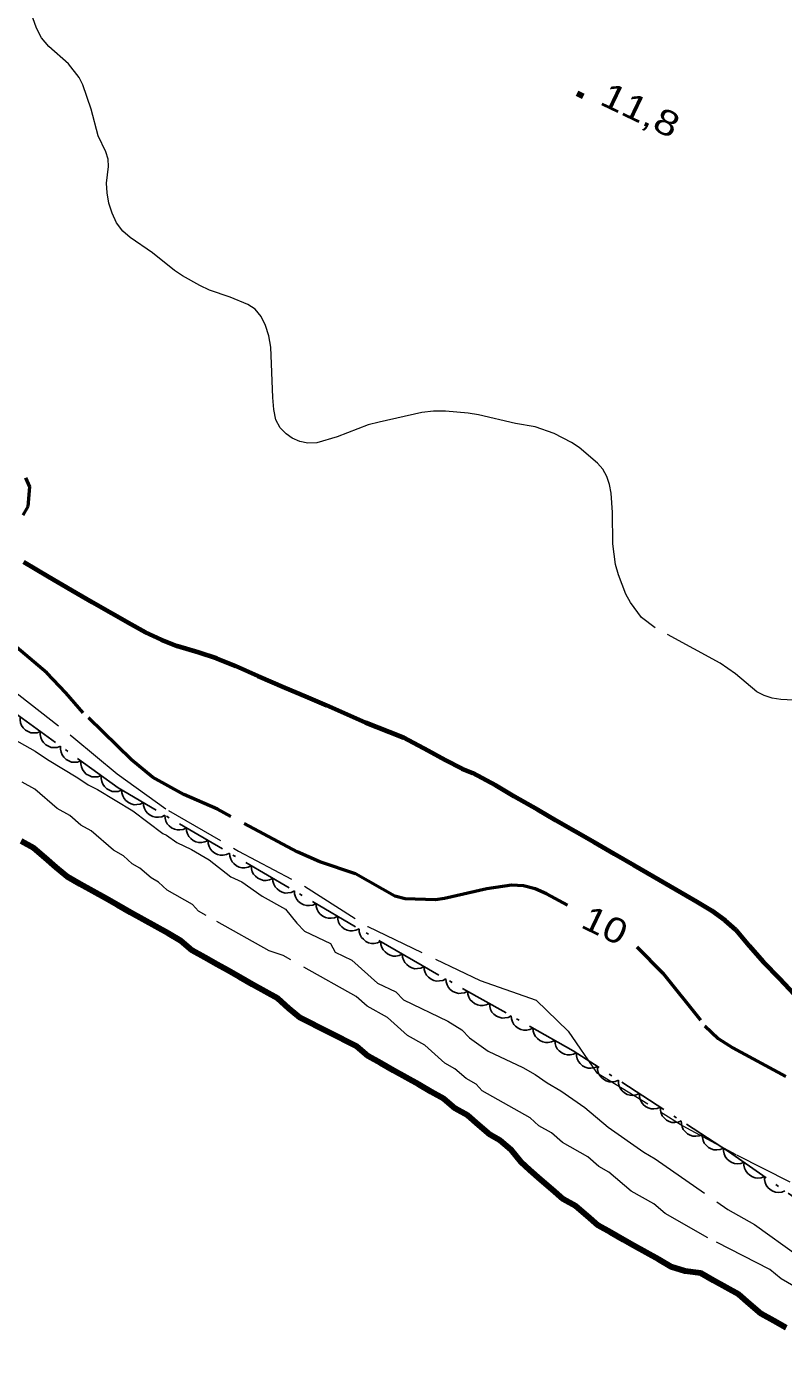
# Model space of a CAD drawing. Extents: x 355726 to 357533, y 5103782 to 5105258.
# Drawn here: x 356113.8 to 356159.2, y 5104614.8 to 5104694.4 of the extents above; entities that cross this region are included whole.
import ezdxf
from ezdxf.enums import TextEntityAlignment as Align

# ---------------------------------------------------------------- set-up
doc = ezdxf.new("R2010")
doc.units = 0
doc.header["$LTSCALE"] = 0.6
for name, pattern in [('DASH_DOUBLE_DOT', [9.2, 5, -1.2, 0.3, -1.2, 0.3, -1.2]), ('DOT_DASHED', [7.7, 5, -1.2, 0.3, -1.2]), ('LONG_DASHED', [7.5, 6, -1.5])]:
    doc.linetypes.add(name, pattern=pattern)
for name, color, linetype, lineweight in [('1', 7, 'LONG_DASHED', 53), ('2', 7, 'LONG_DASHED', 13), ('22', 7, 'Continuous', 13), ('3', 7, 'Continuous', 140), ('4', 7, 'DASH_DOUBLE_DOT', 53), ('44', 7, 'Continuous', 25)]:
    doc.layers.add(name, color=color, linetype=linetype, lineweight=lineweight)

msp = doc.modelspace()

# ---------------------------------------------------------------- linework, layer by layer
at = {"layer": '1'}
for points in [[(356113.61, 5104665.13), (356113.92, 5104665.65), (356114.02, 5104666.84), (356113.78, 5104667.37)], [(356146.26, 5104641.76), (356145, 5104642.44), (356144.32, 5104642.73), (356143.62, 5104642.91), (356142.89, 5104642.96), (356141.42, 5104642.74), (356138.88, 5104642.15), (356138.33, 5104642.07), (356136.52, 5104642.13), (356135.91, 5104642.3), (356133.55, 5104643.63), (356131.4, 5104644.36), (356130.04, 5104644.96), (356125.26, 5104647.51), (356123.25, 5104648.38), (356121.37, 5104649.42), (356120.1, 5104650.46), (356117.22, 5104653.28), (356116.18, 5104654.48), (356115.03, 5104655.69), (356113.22, 5104657.23)], [(356150.42, 5104639.25), (356151.98, 5104637.68), (356154.5, 5104634.53), (356155.29, 5104633.76), (356156.17, 5104633.2), (356161.44, 5104630.36)]]:
    msp.add_lwpolyline(points, dxfattribs=at)
at = {"layer": '2'}
for points in [[(356127.53, 5104677.49), (356127.09, 5104677.76), (356126.02, 5104678.21), (356124.79, 5104678.63), (356124.2, 5104678.9), (356123.16, 5104679.48), (356122.69, 5104679.8), (356121.37, 5104680.86), (356120.03, 5104681.78), (356119.58, 5104682.16), (356119.21, 5104682.67), (356118.94, 5104683.24), (356118.74, 5104683.84), (356118.64, 5104684.46), (356118.6, 5104685.04), (356118.73, 5104686.04), (356118.71, 5104686.48), (356118.57, 5104686.92), (356118.11, 5104687.87), (356117.69, 5104689.47), (356117.2, 5104690.93), (356116.98, 5104691.37), (356116.33, 5104692.19), (356115.15, 5104693.24), (356114.72, 5104693.76), (356114.41, 5104694.34), (356114.2, 5104694.95)], [(356161.17, 5104653.98), (356159.04, 5104654.08), (356158.52, 5104654.16), (356158.05, 5104654.32), (356157.61, 5104654.55), (356156.33, 5104655.63), (356155.42, 5104656.26), (356151.52, 5104658.38), (356150.7, 5104659.01), (356150.03, 5104659.9), (356149.76, 5104660.4), (356149.32, 5104661.55), (356149.14, 5104662.17), (356148.97, 5104663.42), (356148.95, 5104665.3), (356148.88, 5104666.45), (356148.77, 5104666.98), (356148.61, 5104667.46), (356148.38, 5104667.9), (356148.06, 5104668.25), (356146.96, 5104669.19), (356146.49, 5104669.49), (356145.45, 5104670.04), (356144.32, 5104670.43), (356143.13, 5104670.63), (356140.91, 5104671.16), (356140.29, 5104671.26), (356138.93, 5104671.38), (356138.22, 5104671.38), (356137.52, 5104671.3), (356134.96, 5104670.72), (356134.3, 5104670.55), (356132.45, 5104669.84), (356131.22, 5104669.48), (356130.68, 5104669.46), (356130.2, 5104669.55), (356129.75, 5104669.75), (356129.38, 5104670.01), (356129.02, 5104670.37), (356128.76, 5104670.86), (356128.64, 5104671.47), (356128.58, 5104672.19), (356128.46, 5104675.2), (356128.35, 5104675.88), (356128.14, 5104676.51), (356127.89, 5104677.05), (356127.53, 5104677.49)], [(356112.89, 5104654.73), (356116.65, 5104651.79), (356119.24, 5104649.63), (356122.32, 5104647.43), (356126.53, 5104645), (356130.48, 5104642.9), (356134.28, 5104640.47), (356141.02, 5104637.24), (356144.38, 5104636.05), (356146.29, 5104634.2), (356148, 5104631.73), (356153.18, 5104628.53), (356156.38, 5104626.79), (356159.96, 5104624.98)], [(356111.22, 5104652.72), (356114.34, 5104650.99), (356115.07, 5104650.48), (356116.9, 5104649.38), (356117.52, 5104648.96), (356118.07, 5104648.69), (356120.19, 5104647.42), (356121.98, 5104646.05), (356122.2, 5104645.95), (356122.82, 5104645.51), (356123.71, 5104645.09), (356124.77, 5104644.47), (356126.06, 5104643.46), (356126.72, 5104643.15), (356127.95, 5104642.3), (356129.34, 5104641.51), (356130.03, 5104640.67), (356130.49, 5104640.2), (356132.04, 5104639.45), (356132.33, 5104638.93), (356133.33, 5104638.45), (356134.86, 5104637.08), (356135.96, 5104636.55), (356136.42, 5104636.08), (356139.08, 5104634.8), (356139.92, 5104634.28), (356140.37, 5104633.8), (356141.49, 5104633.01), (356143.57, 5104632.02), (356144.32, 5104631.6), (356145.03, 5104631.1), (356145.86, 5104630.63), (356147.29, 5104629.63), (356148.7, 5104628.44), (356150.84, 5104626.94), (356151.52, 5104626.55), (356155.87, 5104623.51), (356157.46, 5104622.62), (356160.08, 5104620.74)], [(356159.82, 5104618.92), (356159.06, 5104619.35), (356158.39, 5104619.92), (356154.68, 5104621.82), (356152.11, 5104623.26), (356151.44, 5104623.84), (356150.08, 5104624.6), (356148.74, 5104625.75), (356148.14, 5104626.09), (356147.47, 5104626.67), (356145.96, 5104627.52), (356145.29, 5104628.1), (356144.53, 5104628.52), (356144.01, 5104629.01), (356141.14, 5104630.63), (356140.77, 5104631.03), (356140.17, 5104631.37), (356139.5, 5104631.95), (356138.89, 5104632.29), (356137.7, 5104633.36), (356136.65, 5104633.95), (356135.46, 5104635.02), (356134.25, 5104635.7), (356133.58, 5104636.27), (356129.2, 5104638.74), (356128.36, 5104639.02), (356124.58, 5104641.14), (356124.13, 5104641.4), (356123.76, 5104641.8), (356122.25, 5104642.65), (356121.73, 5104643.14), (356121.28, 5104643.4), (356120.61, 5104643.97), (356120.15, 5104644.23), (356119.63, 5104644.72), (356119.03, 5104645.06), (356117.69, 5104646.21), (356117.08, 5104646.55), (356116.41, 5104647.13), (356115.66, 5104647.55), (356114.32, 5104648.7), (356113.56, 5104649.13)]]:
    msp.add_lwpolyline(points, dxfattribs=at)
at = {"layer": '22', "linetype": 'LONG_DASHED', "lineweight": 70}
msp.add_lwpolyline([(356159.86, 5104636.4), (356158.98, 5104637.33), (356158.01, 5104638.34), (356157.17, 5104639.3), (356156.34, 5104640.28), (356155.7, 5104640.84), (356154.91, 5104641.41), (356154.02, 5104641.95), (356152.77, 5104642.67), (356151.39, 5104643.48), (356150.26, 5104644.13), (356149.07, 5104644.82), (356147.87, 5104645.51), (356146.71, 5104646.18), (356145.56, 5104646.84), (356144.47, 5104647.47), (356143.05, 5104648.28), (356141.95, 5104648.92), (356140.57, 5104649.66), (356139.94, 5104649.93), (356138.92, 5104650.44), (356137.9, 5104651), (356136.44, 5104651.78), (356135.58, 5104652.13), (356134.17, 5104652.68), (356133.05, 5104653.19), (356131.83, 5104653.73), (356130.56, 5104654.26), (356129.33, 5104654.78), (356127.71, 5104655.49), (356126.36, 5104656.09), (356125.22, 5104656.54), (356124.12, 5104656.9), (356122.85, 5104657.28), (356121.9, 5104657.67), (356120.94, 5104658.11), (356120.08, 5104658.58), (356118.93, 5104659.24), (356117.76, 5104659.91), (356116.53, 5104660.62), (356115.14, 5104661.43), (356113.66, 5104662.32)], dxfattribs=at)
at = {"layer": '3'}
msp.add_line((356146.83, 5104690.43), (356147.19, 5104690.26), dxfattribs=at)
at = {"layer": '4', "linetype": 'Continuous', "lineweight": 90}
for points in [[(356143.99, 5104625.86), (356143.47, 5104626.35), (356142.88, 5104627.08), (356142.21, 5104627.65), (356141.61, 5104627.99), (356140.94, 5104628.57), (356140.27, 5104629.15), (356139.51, 5104629.57), (356138.84, 5104630.15), (356138.08, 5104630.57), (356137.33, 5104631), (356136.57, 5104631.42), (356135.82, 5104631.85), (356135.06, 5104632.28), (356134.3, 5104632.7), (356133.63, 5104633.28), (356130.22, 5104635), (356129.55, 5104635.57), (356128.88, 5104636.15), (356128.13, 5104636.58), (356127.37, 5104637), (356126.61, 5104637.43), (356125.86, 5104637.85), (356125.25, 5104638.19), (356124.5, 5104638.62), (356123.74, 5104639.04), (356123.07, 5104639.62), (356122.32, 5104640.05), (356121.56, 5104640.47), (356120.8, 5104640.9), (356120.05, 5104641.32), (356119.29, 5104641.75), (356118.54, 5104642.17), (356117.78, 5104642.6), (356117.03, 5104643.02), (356116.27, 5104643.45), (356115.6, 5104644.02), (356114.93, 5104644.6), (356114.26, 5104645.18), (356113.5, 5104645.6)], [(356159.37, 5104616.41), (356158.62, 5104616.83), (356157.86, 5104617.26), (356157.19, 5104617.83), (356156.52, 5104618.41), (356155.76, 5104618.84), (356155.01, 5104619.26), (356154.25, 5104619.69), (356153.32, 5104619.81), (356152.48, 5104620.08), (356151.73, 5104620.51), (356150.97, 5104620.94), (356150.22, 5104621.36), (356149.61, 5104621.7), (356148.85, 5104622.13), (356148.1, 5104622.55), (356147.43, 5104623.13), (356146.76, 5104623.71), (356146, 5104624.13), (356145.33, 5104624.71), (356144.66, 5104625.28), (356143.99, 5104625.86)]]:
    msp.add_lwpolyline(points, dxfattribs=at)
at = {"layer": '44', "linetype": 'DOT_DASHED'}
msp.add_lwpolyline([(356173.31, 5104614.82), (356155.91, 5104626.99), (356146.6, 5104633.03), (356137.54, 5104638.13), (356119.3, 5104648.79), (356111.96, 5104654.11), (356105.36, 5104658.62), (356100.57, 5104662.11), (356094.1, 5104666.15), (356087.33, 5104670.35), (356082.24, 5104674.01), (356078.19, 5104676.69), (356069.01, 5104682.26)], dxfattribs=at)
at = {"layer": '44'}
for points in [[(356114.65, 5104652.16), (356114.45, 5104652.09), (356114.25, 5104652.08), (356114.08, 5104652.09), (356113.92, 5104652.16), (356113.76, 5104652.25), (356113.62, 5104652.39), (356113.52, 5104652.52), (356113.46, 5104652.68), (356113.43, 5104652.86), (356113.43, 5104653.04)], [(356115.86, 5104651.28), (356115.66, 5104651.21), (356115.46, 5104651.2), (356115.3, 5104651.21), (356115.13, 5104651.28), (356114.97, 5104651.37), (356114.84, 5104651.51), (356114.74, 5104651.64), (356114.68, 5104651.8), (356114.64, 5104651.98), (356114.65, 5104652.16)], [(356117.07, 5104650.4), (356116.88, 5104650.33), (356116.68, 5104650.32), (356116.51, 5104650.33), (356116.35, 5104650.4), (356116.19, 5104650.49), (356116.05, 5104650.63), (356115.95, 5104650.76), (356115.89, 5104650.92), (356115.85, 5104651.1), (356115.86, 5104651.28)], [(356118.29, 5104649.52), (356118.09, 5104649.45), (356117.89, 5104649.44), (356117.73, 5104649.45), (356117.56, 5104649.52), (356117.4, 5104649.61), (356117.27, 5104649.75), (356117.17, 5104649.88), (356117.11, 5104650.04), (356117.07, 5104650.22), (356117.07, 5104650.4)], [(356119.5, 5104648.64), (356119.31, 5104648.57), (356119.1, 5104648.56), (356118.94, 5104648.57), (356118.78, 5104648.64), (356118.62, 5104648.73), (356118.48, 5104648.87), (356118.38, 5104649), (356118.32, 5104649.16), (356118.28, 5104649.34), (356118.29, 5104649.52)], [(356120.81, 5104647.91), (356120.62, 5104647.82), (356120.42, 5104647.79), (356120.26, 5104647.78), (356120.09, 5104647.83), (356119.92, 5104647.91), (356119.77, 5104648.03), (356119.66, 5104648.15), (356119.58, 5104648.31), (356119.53, 5104648.48), (356119.52, 5104648.66)], [(356122.11, 5104647.15), (356121.92, 5104647.06), (356121.72, 5104647.03), (356121.55, 5104647.03), (356121.38, 5104647.07), (356121.22, 5104647.15), (356121.07, 5104647.27), (356120.96, 5104647.39), (356120.88, 5104647.55), (356120.82, 5104647.73), (356120.81, 5104647.91)], [(356123.4, 5104646.39), (356123.21, 5104646.3), (356123.01, 5104646.27), (356122.85, 5104646.27), (356122.68, 5104646.32), (356122.51, 5104646.39), (356122.36, 5104646.52), (356122.25, 5104646.63), (356122.17, 5104646.79), (356122.12, 5104646.97), (356122.11, 5104647.15)], [(356124.7, 5104645.64), (356124.51, 5104645.55), (356124.31, 5104645.51), (356124.14, 5104645.51), (356123.97, 5104645.56), (356123.81, 5104645.64), (356123.66, 5104645.76), (356123.55, 5104645.88), (356123.47, 5104646.04), (356123.41, 5104646.21), (356123.4, 5104646.39)], [(356125.99, 5104644.88), (356125.8, 5104644.79), (356125.6, 5104644.76), (356125.44, 5104644.75), (356125.27, 5104644.8), (356125.1, 5104644.88), (356124.95, 5104645), (356124.84, 5104645.12), (356124.76, 5104645.28), (356124.71, 5104645.46), (356124.7, 5104645.64)], [(356127.29, 5104644.12), (356127.1, 5104644.03), (356126.9, 5104644), (356126.73, 5104644), (356126.56, 5104644.04), (356126.4, 5104644.12), (356126.25, 5104644.25), (356126.14, 5104644.36), (356126.06, 5104644.52), (356126, 5104644.7), (356125.99, 5104644.88)], [(356128.58, 5104643.36), (356128.39, 5104643.27), (356128.19, 5104643.24), (356128.03, 5104643.24), (356127.86, 5104643.29), (356127.69, 5104643.37), (356127.54, 5104643.49), (356127.43, 5104643.61), (356127.35, 5104643.76), (356127.3, 5104643.94), (356127.29, 5104644.12)], [(356129.88, 5104642.61), (356129.69, 5104642.52), (356129.49, 5104642.49), (356129.32, 5104642.48), (356129.15, 5104642.53), (356128.99, 5104642.61), (356128.84, 5104642.73), (356128.73, 5104642.85), (356128.65, 5104643.01), (356128.59, 5104643.19), (356128.58, 5104643.36)], [(356131.17, 5104641.85), (356130.98, 5104641.76), (356130.78, 5104641.73), (356130.62, 5104641.73), (356130.45, 5104641.77), (356130.28, 5104641.85), (356130.13, 5104641.98), (356130.02, 5104642.09), (356129.94, 5104642.25), (356129.89, 5104642.43), (356129.88, 5104642.61)], [(356132.47, 5104641.09), (356132.28, 5104641), (356132.08, 5104640.97), (356131.91, 5104640.97), (356131.74, 5104641.02), (356131.58, 5104641.1), (356131.43, 5104641.22), (356131.32, 5104641.34), (356131.24, 5104641.49), (356131.18, 5104641.67), (356131.17, 5104641.85)], [(356133.76, 5104640.34), (356133.57, 5104640.25), (356133.37, 5104640.22), (356133.21, 5104640.21), (356133.04, 5104640.26), (356132.87, 5104640.34), (356132.72, 5104640.46), (356132.61, 5104640.58), (356132.53, 5104640.74), (356132.48, 5104640.91), (356132.47, 5104641.09)], [(356135.06, 5104639.58), (356134.87, 5104639.49), (356134.67, 5104639.46), (356134.5, 5104639.46), (356134.33, 5104639.5), (356134.17, 5104639.58), (356134.02, 5104639.71), (356133.91, 5104639.82), (356133.83, 5104639.98), (356133.77, 5104640.16), (356133.76, 5104640.34)], [(356136.35, 5104638.82), (356136.16, 5104638.73), (356135.96, 5104638.7), (356135.8, 5104638.7), (356135.63, 5104638.75), (356135.46, 5104638.83), (356135.32, 5104638.95), (356135.2, 5104639.07), (356135.12, 5104639.22), (356135.07, 5104639.4), (356135.06, 5104639.58)], [(356137.65, 5104638.07), (356137.46, 5104637.98), (356137.26, 5104637.95), (356137.09, 5104637.94), (356136.92, 5104637.99), (356136.76, 5104638.07), (356136.61, 5104638.19), (356136.5, 5104638.31), (356136.42, 5104638.47), (356136.36, 5104638.64), (356136.35, 5104638.82)], [(356138.96, 5104637.33), (356138.77, 5104637.24), (356138.57, 5104637.21), (356138.4, 5104637.2), (356138.23, 5104637.24), (356138.07, 5104637.32), (356137.92, 5104637.44), (356137.8, 5104637.56), (356137.72, 5104637.71), (356137.66, 5104637.89), (356137.65, 5104638.07)], [(356140.26, 5104636.6), (356140.08, 5104636.5), (356139.88, 5104636.47), (356139.71, 5104636.46), (356139.54, 5104636.51), (356139.37, 5104636.58), (356139.22, 5104636.7), (356139.11, 5104636.82), (356139.03, 5104636.98), (356138.97, 5104637.15), (356138.96, 5104637.33)], [(356141.57, 5104635.86), (356141.38, 5104635.77), (356141.18, 5104635.73), (356141.02, 5104635.73), (356140.85, 5104635.77), (356140.68, 5104635.85), (356140.53, 5104635.97), (356140.42, 5104636.08), (356140.33, 5104636.24), (356140.28, 5104636.42), (356140.26, 5104636.6)], [(356142.88, 5104635.13), (356142.69, 5104635.03), (356142.49, 5104635), (356142.33, 5104634.99), (356142.15, 5104635.04), (356141.99, 5104635.11), (356141.84, 5104635.23), (356141.72, 5104635.35), (356141.64, 5104635.51), (356141.59, 5104635.68), (356141.57, 5104635.86)], [(356144.18, 5104634.39), (356144, 5104634.3), (356143.8, 5104634.26), (356143.63, 5104634.26), (356143.46, 5104634.3), (356143.29, 5104634.38), (356143.14, 5104634.5), (356143.03, 5104634.61), (356142.95, 5104634.77), (356142.89, 5104634.95), (356142.88, 5104635.13)], [(356145.49, 5104633.65), (356145.3, 5104633.56), (356145.1, 5104633.53), (356144.94, 5104633.52), (356144.77, 5104633.56), (356144.6, 5104633.64), (356144.45, 5104633.76), (356144.34, 5104633.88), (356144.26, 5104634.03), (356144.2, 5104634.21), (356144.18, 5104634.39)], [(356146.8, 5104632.92), (356146.61, 5104632.82), (356146.41, 5104632.79), (356146.25, 5104632.78), (356146.08, 5104632.83), (356145.91, 5104632.91), (356145.76, 5104633.03), (356145.64, 5104633.14), (356145.56, 5104633.3), (356145.51, 5104633.47), (356145.49, 5104633.65)], [(356148.05, 5104632.09), (356147.86, 5104632.01), (356147.66, 5104631.99), (356147.49, 5104631.99), (356147.32, 5104632.05), (356147.16, 5104632.13), (356147.02, 5104632.26), (356146.91, 5104632.38), (356146.84, 5104632.55), (356146.8, 5104632.73), (356146.79, 5104632.91)], [(356149.31, 5104631.27), (356149.12, 5104631.19), (356148.91, 5104631.17), (356148.75, 5104631.17), (356148.58, 5104631.23), (356148.42, 5104631.32), (356148.28, 5104631.45), (356148.17, 5104631.57), (356148.1, 5104631.73), (356148.05, 5104631.91), (356148.05, 5104632.09)], [(356150.57, 5104630.46), (356150.37, 5104630.38), (356150.17, 5104630.35), (356150.01, 5104630.36), (356149.84, 5104630.41), (356149.68, 5104630.5), (356149.54, 5104630.63), (356149.43, 5104630.75), (356149.36, 5104630.91), (356149.31, 5104631.09), (356149.31, 5104631.27)], [(356151.82, 5104629.64), (356151.63, 5104629.56), (356151.43, 5104629.54), (356151.27, 5104629.54), (356151.1, 5104629.6), (356150.94, 5104629.68), (356150.79, 5104629.81), (356150.69, 5104629.94), (356150.62, 5104630.1), (356150.57, 5104630.28), (356150.57, 5104630.46)], [(356153.08, 5104628.82), (356152.89, 5104628.74), (356152.69, 5104628.72), (356152.52, 5104628.73), (356152.36, 5104628.78), (356152.19, 5104628.87), (356152.05, 5104629), (356151.94, 5104629.12), (356151.87, 5104629.28), (356151.83, 5104629.46), (356151.82, 5104629.64)], [(356154.34, 5104628.01), (356154.15, 5104627.93), (356153.95, 5104627.9), (356153.78, 5104627.91), (356153.61, 5104627.96), (356153.45, 5104628.05), (356153.31, 5104628.18), (356153.2, 5104628.3), (356153.13, 5104628.46), (356153.09, 5104628.64), (356153.08, 5104628.82)], [(356155.6, 5104627.19), (356155.41, 5104627.11), (356155.21, 5104627.09), (356155.04, 5104627.09), (356154.87, 5104627.15), (356154.71, 5104627.23), (356154.57, 5104627.36), (356154.46, 5104627.49), (356154.39, 5104627.65), (356154.35, 5104627.83), (356154.34, 5104628.01)], [(356156.84, 5104626.34), (356156.64, 5104626.27), (356156.44, 5104626.25), (356156.27, 5104626.26), (356156.11, 5104626.32), (356155.95, 5104626.42), (356155.81, 5104626.55), (356155.71, 5104626.68), (356155.64, 5104626.84), (356155.6, 5104627.02), (356155.61, 5104627.2)], [(356158.07, 5104625.48), (356157.87, 5104625.41), (356157.67, 5104625.39), (356157.5, 5104625.4), (356157.34, 5104625.46), (356157.18, 5104625.56), (356157.04, 5104625.69), (356156.94, 5104625.82), (356156.87, 5104625.98), (356156.83, 5104626.16), (356156.84, 5104626.34)], [(356159.29, 5104624.62), (356159.1, 5104624.55), (356158.9, 5104624.53), (356158.73, 5104624.54), (356158.57, 5104624.6), (356158.41, 5104624.7), (356158.27, 5104624.83), (356158.17, 5104624.96), (356158.1, 5104625.12), (356158.06, 5104625.3), (356158.07, 5104625.48)]]:
    msp.add_lwpolyline(points, dxfattribs=at)

# ---------------------------------------------------------------- texts
at = {"layer": '1', "width": 1.2}
msp.add_text('10', height=1.5, rotation=334.435, dxfattribs=at).set_placement((356148.181, 5104639.875), align=Align.CENTER)
at = {"layer": '3', "width": 1.25}
msp.add_text('11,8   ', height=1.5, rotation=334.423, dxfattribs=at).set_placement((356148.11, 5104689.8))

doc.saveas('drawing.dxf')
